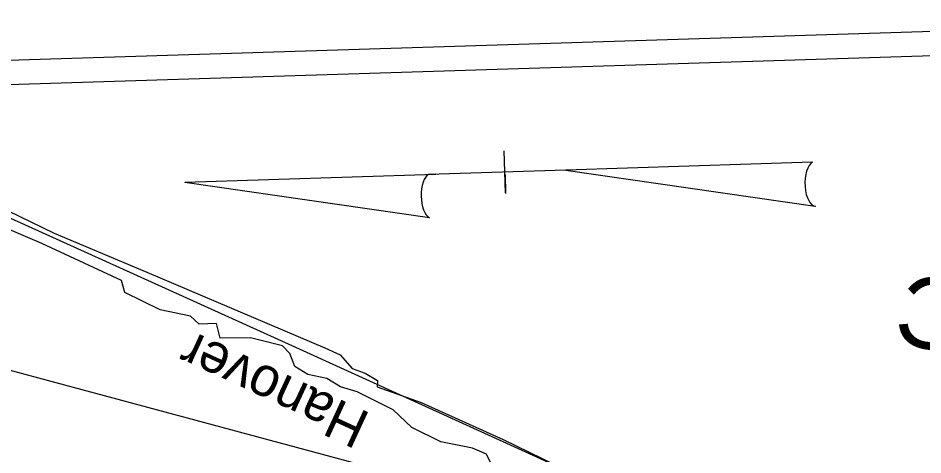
# Model space of a CAD drawing. Extents: x 2308163 to 2335412, y -96774 to 127732.
# Drawn here: x 2326033 to 2326312.3, y 123340.9 to 123475.7 of the extents above; entities that cross this region are included whole.
import ezdxf

# ---------------------------------------------------------------- set-up
doc = ezdxf.new("R2010")
doc.units = 0
for name, color, linetype in [('Default', 7, 'Continuous'), ('Old_Level_1', 7, 'Continuous'), ('Old_Level_19', 7, 'Continuous'), ('Old_Level_21', 7, 'Continuous'), ('Old_Level_52', 7, 'Continuous'), ('Old_Level_60', 7, 'Continuous'), ('Old_Level_63', 7, 'Continuous'), ('Prop North Arrow for Plan Sheets CELL', 7, 'Continuous')]:
    doc.layers.add(name, color=color, linetype=linetype)

# ---------------------------------------------------------------- blocks, each defined once
blk = doc.blocks.new('North Arrow for Plan Sheets-E')
at = {"layer": 'Prop North Arrow for Plan Sheets CELL'}
for p, q in [((-0.1659, 0.293), (-0.0019, 1.22)), ((-0.0009, 1.22), (-0.0019, 1.22)), ((-0.0009, 1.22), (-0.0019, 1.22)), ((-0.0009, 1.22), (-0.0009, 0.264)), ((-0.0009, -0.232), (-0.0009, 0.292)), ((-0.0009, 0.264), (-0.0009, 0.291)), ((-0.0809, 0), (-0.0819, 0)), ((-0.0099, 0), (-0.0809, 0)), ((-0.0799, 0), (0.0801, 0)), ((-0.0009, -0.232), (-0.1679, -1.177)), ((0.0001, -1.173), (-0.0009, -0.232))]:
    blk.add_line(p, q, dxfattribs=at)
for centre, start_param, end_param in [((-0.0832, 0.2831), 0.216388, 2.908219), ((-0.0832, -1.1803), 0.201328, 3.141593)]:
    blk.add_ellipse(centre, major_axis=(0.0846, -0.0006), ratio=0.461098, start_param=start_param, end_param=end_param, dxfattribs=at)

msp = doc.modelspace()

# ---------------------------------------------------------------- linework, layer by layer
at = {"layer": 'Old_Level_1'}
for p, q in [((2325949.48, 123460.16), (2326443.34, 123475.72)), ((2325949.72, 123452.66), (2326443.57, 123468.22))]:
    msp.add_line(p, q, dxfattribs=at)
at = {"layer": 'Old_Level_52'}
msp.add_lwpolyline([(2326352.46, 123278.37), (2326344.49, 123279.39), (2326334.11, 123277.47), (2326314.41, 123278.3), (2326300.12, 123278.02), (2326291.22, 123283.57), (2326287.11, 123292.06), (2326280.06, 123298.67), (2326266.15, 123306.08), (2326194.23, 123339.67), (2326117.56, 123374.58), (2325996.97, 123429.09), (2325967.84, 123440.3), (2325941.49, 123450.31)], dxfattribs=at)
at = {"layer": 'Old_Level_60'}
for points in [[(2325943.78, 123451.42), (2325950.75, 123448.77), (2325974.15, 123440.27), (2325991.46, 123433.15), (2326015.22, 123423.35), (2326044.14, 123409.29), (2326072.73, 123397.29), (2326127.66, 123373.96)], [(2326179.29, 123337.5), (2326177.6, 123341.14), (2326173.26, 123342.95), (2326163.49, 123344.95), (2326154.57, 123349.39), (2326148.8, 123354.84), (2326137.6, 123360.36), (2326132.53, 123361.86), (2326128.26, 123364.49), (2326122.4, 123365.69), (2326118.44, 123368.15), (2326116.87, 123372.18), (2326114.62, 123374.57), (2326104.7, 123377), (2326095.31, 123376.92), (2326094.24, 123381.45), (2326088.92, 123381.22), (2326086.15, 123383.76), (2326076.82, 123385.72), (2326065.98, 123390.99), (2326064.88, 123394.7), (2326040.36, 123406.16), (2325988.84, 123428.14)], [(2326127.66, 123373.96), (2326132.4, 123371.8), (2326136.14, 123367.53), (2326140.13, 123366.07), (2326143.93, 123363.85), (2326143.86, 123361.92), (2326157.43, 123357.03), (2326182.68, 123345.67), (2326202.81, 123335.85), (2326223.69, 123325.46), (2326232.34, 123320.74), (2326241.56, 123317.67)]]:
    msp.add_lwpolyline(points, dxfattribs=at)
at = {"layer": 'Old_Level_63'}
msp.add_lwpolyline([(2326475.8, 123239.36), (2326422.14, 123261.61), (2325934.09, 123392.92)], dxfattribs=at)

# ---------------------------------------------------------------- block references
at = {"layer": 'Default', "xscale": 81, "yscale": 81, "rotation": 91.80479200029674}
msp.add_blockref('North Arrow for Plan Sheets-E', (2326183.26, 123428.24), dxfattribs=at)

# ---------------------------------------------------------------- texts
at = {"layer": 'Old_Level_19'}
msp.add_text('Hanover', height=12.145, rotation=155.1566, dxfattribs=at).set_placement((2326142.2, 123353.54))
at = {"layer": 'Old_Level_21'}
msp.add_text('ATLANTIC', height=21.862, rotation=164.9405, dxfattribs=at).set_placement((2326444.48, 123360.97))

doc.saveas('drawing.dxf')
